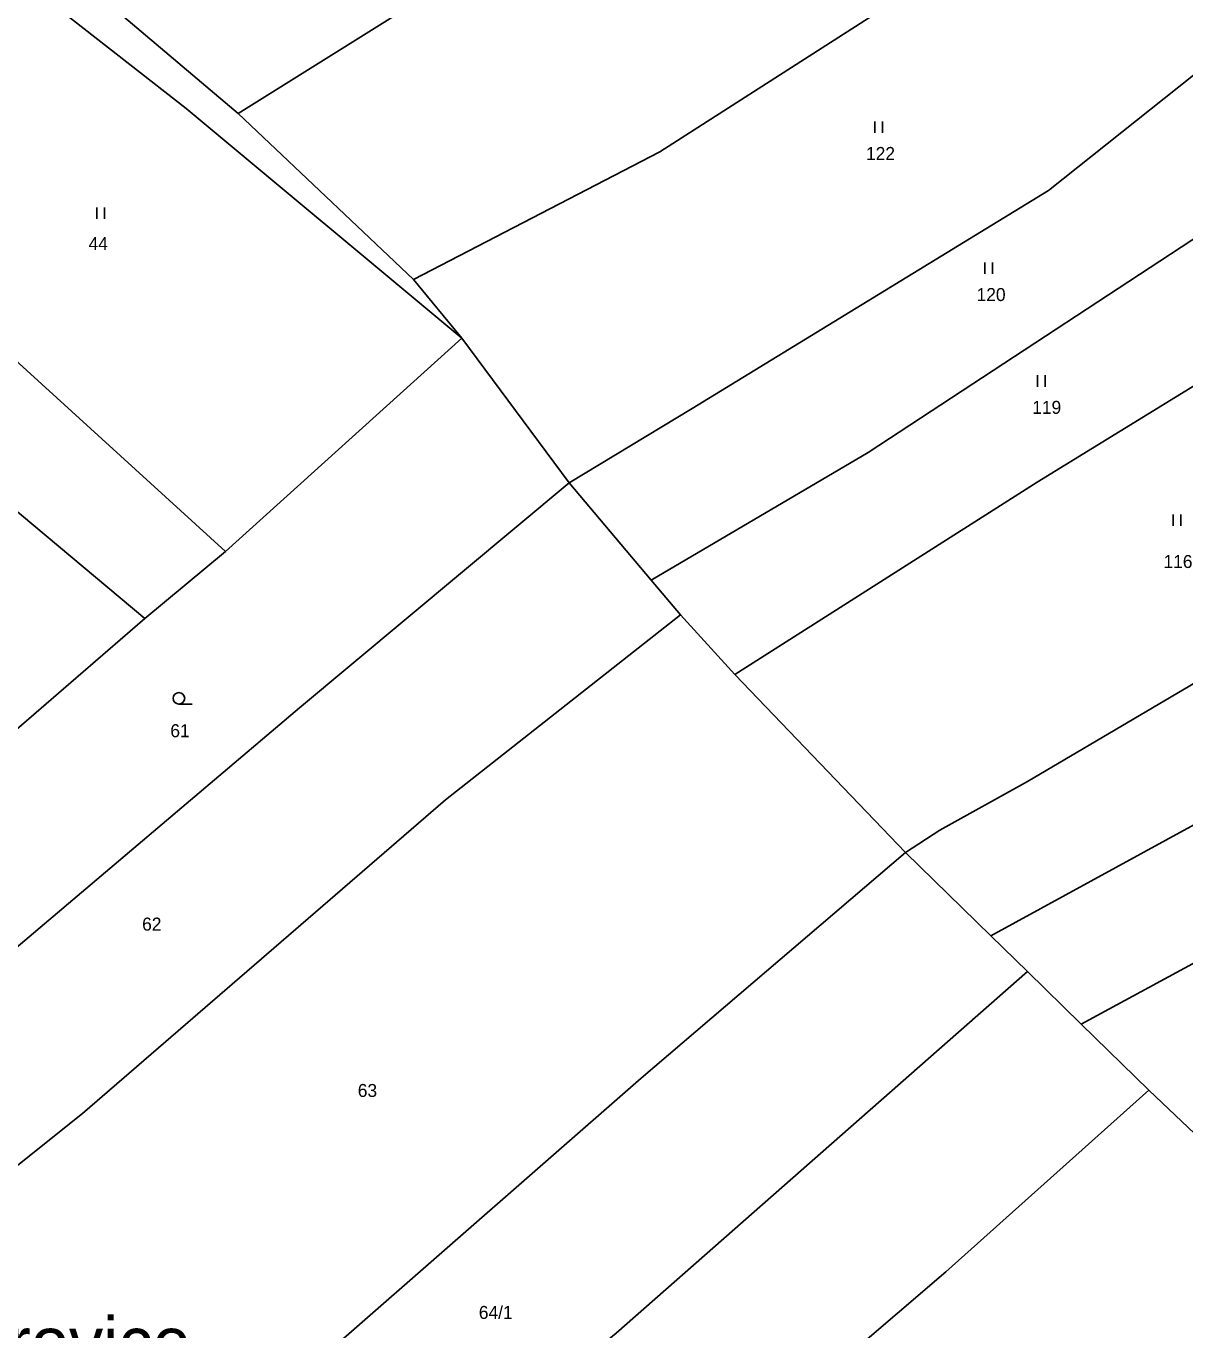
# Model space of a CAD drawing. Extents: x -751333 to -746055, y -1133395 to -1129777.
# Drawn here: x -747698.2 to -747546.5, y -1131157.3 to -1130986.6 of the extents above; entities that cross this region are included whole.
import ezdxf

# ---------------------------------------------------------------- set-up
doc = ezdxf.new("R2010")
doc.units = 0
for name, color, linetype in [('Hranice parcel', 7, 'Continuous'), ('Parcelní čísla', 7, 'Continuous'), ('Pop  PČ popisy', 7, 'Continuous'), ('Značky kultur', 7, 'Continuous')]:
    doc.layers.add(name, color=color, linetype=linetype)

msp = doc.modelspace()

# ---------------------------------------------------------------- linework, layer by layer
at = {"layer": 'Hranice parcel'}
for p, q in [((-747670.43, -1130998.05), (-747602.88, -1130955.82)), ((-747670.43, -1130998.05), (-747696.99, -1130975.53)), ((-747647.48, -1131019.78), (-747670.43, -1130998.05)), ((-747713.52, -1131017.65), (-747672.07, -1131055.39)), ((-747641.15, -1131027.46), (-747647.48, -1131019.78)), ((-747672.07, -1131055.39), (-747641.15, -1131027.46)), ((-747627.11, -1131046.39), (-747641.15, -1131027.46)), ((-747704.02, -1131046.27), (-747682.65, -1131064.18)), ((-747616.38, -1131059.15), (-747627.11, -1131046.39)), ((-747682.65, -1131064.18), (-747672.07, -1131055.39)), ((-747612.55, -1131063.71), (-747616.38, -1131059.15)), ((-747605.42, -1131071.52), (-747612.55, -1131063.71)), ((-747702.76, -1131081.57), (-747682.65, -1131064.18)), ((-747583.1, -1131094.79), (-747605.42, -1131071.52)), ((-747571.91, -1131105.73), (-747583.1, -1131094.79)), ((-747567.13, -1131110.4), (-747571.91, -1131105.73)), ((-747560.11, -1131117.26), (-747567.13, -1131110.4)), ((-747560.11, -1131117.26), (-747551.23, -1131125.94)), ((-747551.23, -1131125.94), (-747534.94, -1131141.41))]:
    msp.add_line(p, q, dxfattribs=at)
for points in [[(-747647.48, -1131019.78), (-747615.24, -1131003.06), (-747568.39, -1130973)], [(-747641.15, -1131027.46), (-747677.24, -1130997.39), (-747699.35, -1130980.06), (-747727.26, -1130987.09)], [(-747537.72, -1130986.92), (-747564.39, -1131008.14), (-747611.03, -1131036.67), (-747627.11, -1131046.39)], [(-747536.11, -1131008.38), (-747587.97, -1131042.46), (-747616.38, -1131059.15)], [(-747521.83, -1131019.25), (-747565.86, -1131046.34), (-747605.42, -1131071.52)], [(-747722.98, -1131126.94), (-747702.08, -1131109.45), (-747662.38, -1131075.87), (-747627.11, -1131046.39)], [(-747506.57, -1131049.83), (-747567.11, -1131085.51), (-747578.6, -1131091.89), (-747583.1, -1131094.79)], [(-747726.24, -1131157.28), (-747690.81, -1131128.96), (-747643.31, -1131087.92), (-747612.55, -1131063.71)], [(-747497.04, -1131064.23), (-747519.1, -1131076.81), (-747571.91, -1131105.73)], [(-747478.83, -1131075.18), (-747493.05, -1131080.92), (-747560.11, -1131117.26)], [(-747693.71, -1131188.35), (-747673.39, -1131172.41), (-747656.27, -1131158.12), (-747617.7, -1131124.35), (-747583.1, -1131094.79)], [(-747678.94, -1131204.15), (-747651.91, -1131183.16), (-747620.97, -1131157.74), (-747567.13, -1131110.4)], [(-747663.87, -1131220.26), (-747622.68, -1131188.16), (-747577.82, -1131149.69), (-747551.23, -1131125.94)]]:
    msp.add_lwpolyline(points, dxfattribs=at)
at = {"layer": 'Značky kultur'}
for p, q in [((-747587.121, -1131000.59), (-747587.121, -1130999.09)), ((-747586.12, -1131000.59), (-747586.12, -1130999.09)), ((-747688.921, -1131011.86), (-747688.921, -1131010.36)), ((-747687.92, -1131011.86), (-747687.92, -1131010.36)), ((-747572.691, -1131019.06), (-747572.691, -1131017.56)), ((-747571.69, -1131019.06), (-747571.69, -1131017.56)), ((-747565.811, -1131033.83), (-747565.811, -1131032.33)), ((-747564.81, -1131033.83), (-747564.81, -1131032.33)), ((-747548.071, -1131052.06), (-747548.071, -1131050.56)), ((-747547.07, -1131052.06), (-747547.07, -1131050.56)), ((-747678.173, -1131075.37), (-747676.423, -1131075.37))]:
    msp.add_line(p, q, dxfattribs=at)
msp.add_circle((-747678.173, -1131074.62), 0.75, dxfattribs=at)

# ---------------------------------------------------------------- texts
at = {"layer": 'Parcelní čísla'}
for s, p in [('122', (-747588.26, -1131004.14)), ('44', (-747690, -1131015.94)), ('120', (-747573.79, -1131022.61)), ('119', (-747566.51, -1131037.38)), ('116', (-747549.33, -1131057.56)), ('61', (-747679.3, -1131079.71)), ('62', (-747682.99, -1131105.03)), ('63', (-747654.77, -1131126.81)), ('64/1', (-747638.93, -1131155.87))]:
    msp.add_text(s, height=1.7, dxfattribs=at).set_placement(p)
at = {"layer": 'Pop  PČ popisy'}
msp.add_text('Bežerovice', height=6.7, dxfattribs=at).set_placement((-747720.953, -1131162.31))

doc.saveas('drawing.dxf')
